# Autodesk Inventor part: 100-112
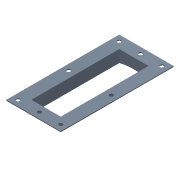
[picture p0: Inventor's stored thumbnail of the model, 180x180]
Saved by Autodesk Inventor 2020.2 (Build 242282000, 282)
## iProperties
Created: 2011-01
Part Number: 100-112
Document SubType Name: Modeling
Designer: F.Stasiak
Density: 1 g/cm^3
Material: Ogólny
Appearance: Stalowoniebieska
Company: Fabian Stasiak CAD Consulting
Manager: www.cadconsulting.pl
Author: F.Stasiak
Subject: Zbiór ćwiczeń. Autodesk Inventor 2020. Kurs podstawowy
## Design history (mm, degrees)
sketch "Szkic1"
  geometry: L1 (50, -150)-(-50, -150); L2 (-50, -150)-(-50, 150); L3 (-50, 150)-(50, 150); L4 (50, 150)-(50, -150); L5 (53, -153)-(-53, -153); L6 (-53, -153)-(-53, 153); L7 (-53, 153)-(53, 153); L8 (53, 153)-(53, -153); 3 further points
  constraints: 16 end point, 4 parallel, 2 midpoint, 2 perpendicular, 1 horizontal, 1 horizontal alignment, 1 vertical alignment, 3 other
  dimensions: "d0" = 100 distance of L2.end L3.end; "d1" = 300 distance of L1.end L2.end; "d2" = 3 distance between parallel lines of L8 L4
extrude "Wyciągnięcie proste1" new body sketch "Szkic1" distance "d3" = 100; taper "d4" = 0 deg
sketch "Szkic2"
  geometry: L1 (-50, -150)-(-50, 150) reference; L2 (-50, 150)-(50, 150) reference; L3 (50, 150)-(50, -150) reference; L4 (50, -150)-(-50, -150) reference; L5 (-53, -153)-(-53, 153) reference; L6 (53, -153)-(-53, -153) reference; L7 (53, 153)-(53, -153) reference; L8 (-53, 153)-(53, 153) reference; L9 (-93, 193)-(-93, -193); L10 (-93, -193)-(93, -193); L11 (93, -193)-(93, 193); L12 (93, 193)-(-93, 193); 1 further point
  constraints: 8 end point, 3 other
  dimensions: "d5" = 40 distance between parallel lines of L9 L5
extrude "Wyciągnięcie proste2" join sketch "Szkic2" distance "d6" = 3; taper "d7" = 0 deg
sketch "Szkic3"
  geometry: L1 (93, -193)-(93, 193) reference; L2 (-93, -193)-(93, -193) reference; L3 (-93, 193)-(-93, -193) reference; L4 (93, 193)-(-93, 193) reference; L5 (73, -173)-(73, 173); L6 (73, 173)-(-73, 173); L7 (-73, 173)-(-73, -173); L8 (-73, -173)-(73, -173); 8 further points
  constraints: 8 end point, 4 midpoint, 3 coincident, 3 other
  dimensions: "d8" = 20 distance between parallel lines of L1 L5
hole "Hole2" sketch "Szkic3" diameter "d16" = 13; stored, may be unused: countersink angle "d20" = 90 deg, drill point angle "d22" = 118 deg; dims "d17" = 6, "d18" = 4, "d19" = 2, "d21" = 8
sketch "Szkic4"
  geometry: L1 (0, 0)-(106, 0) reference; C1 r 200 at (53, 135); 2 further points
  constraints: 1 centre point, 1 midpoint, 1 vertical alignment
  dimensions: "d25" = 400 diameter of C1; "d26" = 135 distance from line of L1 C1.centre
extrude "Wyciągnięcie proste3" cut sketch "Szkic4" extent not by distance; stored distance "d27" = 0; taper "d28" = 0 deg
node "Bryła1"
node "Pętla rzutowana1"
